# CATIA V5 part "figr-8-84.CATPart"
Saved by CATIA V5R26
Part number: Part1
Bounding box of the stored display mesh (mm): x -44.701 to 35.128, y -35.23 to 15.392, z -47.191 to 31.322
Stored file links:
  D:\_Deepak\CATIA\CATIA V5-6R2016_Deepak\Resources\Part files\Partfiles\c08_catia_v5_6r2016_prt\figr-8-84.CATPart
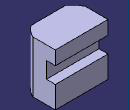
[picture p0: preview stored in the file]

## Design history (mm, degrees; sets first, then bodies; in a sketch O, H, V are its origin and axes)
Body1 (main body)
  Sketch1 on xy-plane, origin (0, 0, 0), H (1, 0, 0), V (0, 1, 0)
    line L1 (-44.7013, 25.8759) -> (35.1284, 25.8759)
    line L2 (35.1284, 25.8759) -> (35.1284, -18.9612)
    line L3 (-44.7013, 25.8759) -> (-44.7013, -18.9612)
    arc A1 centre (-4.7865, 1.0752) radius 44.6615 from (-44.7013, -18.9612) to (35.1284, -18.9612) ccw
    horizontal: L1 H
    vertical: L2 V, L3 V
  Sketch2 on yz-plane, origin (0, 0, 0), H (0, 1, 0), V (0, 0, 1)
    line L1 (-35.2302, 31.3221) -> (-35.2302, -47.1914)
    point P2 (-35.2302, -47.1914)
    point P3 (-35.2302, -47.1914)
    line L2 (-35.2302, -47.1914) -> (15.3919, -47.1914)
    point P4 (15.3919, -47.1914)
    line L3 (15.3919, 31.3221) -> (-35.2302, 31.3221)
    line L4 (15.3919, 31.3221) -> (15.3919, 10.6589)
    line L5 (15.3919, 10.6589) -> (1.7321, 10.6589)
    line L6 (1.7321, 10.6589) -> (1.7321, -13.9018)
    line L7 (1.7321, -13.9018) -> (15.3919, -13.9018)
    point P9 (15.3919, -13.9018)
    line L8 (15.3919, -13.9018) -> (15.3919, -47.1914)
    point P10 (15.3919, -47.1914)
    vertical: L1 V, L4 V, L6 V, L8 V
    horizontal: L2 H, L3 H, L5 H, L7 H
    coincidence: P9 L4, P10 L2, P10 P4, P3 P2
  SolidCombine1: FirstComponentDirection Sketch1, FirstComponentProfile Sketch1, SecondComponentDirection Sketch2, SecondComponentProfile Sketch2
